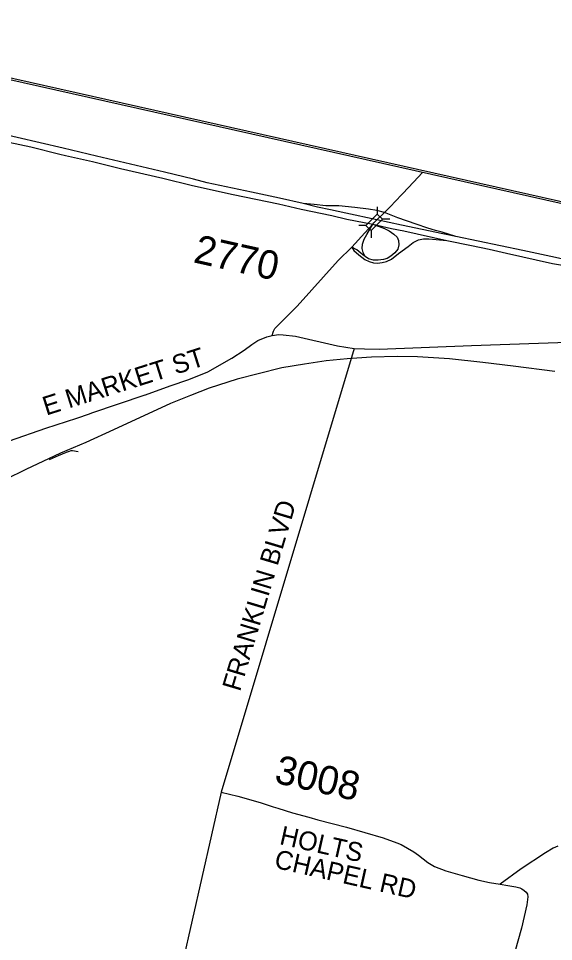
# Model space of a CAD drawing. Extents: x 1784499 to 1786147, y 841097 to 842538.
# Drawn here: x 1784675.3 to 1784800.3, y 842322.5 to 842538 of the extents above; entities that cross this region are included whole.
import ezdxf

# ---------------------------------------------------------------- set-up
doc = ezdxf.new("R2010")
doc.units = 0
for name, color, linetype in [('Exist Railroad Mainline', 7, 'Continuous'), ('Exist Railroad Siding', 7, 'Continuous'), ('Exist Road Primary US Divided Attributed', 7, 'Continuous'), ('Exist Road Primary US Ramp 1 Lane  Attributed', 7, 'Continuous'), ('Exist Road Secondary Structure Standard Bridge CELL', 7, 'Continuous'), ('Exist Road Secondary Type 51 Attributed', 7, 'Continuous'), ('Exist Road Secondary Type 51 Number Label', 7, 'Continuous'), ('Old_Level_40', 7, 'Continuous'), ('Prop DSN Text', 7, 'Continuous'), ('Scratch_Level_3', 7, 'Continuous')]:
    doc.layers.add(name, color=color, linetype=linetype)

msp = doc.modelspace()

# ---------------------------------------------------------------- linework, layer by layer
at = {"layer": 'Exist Railroad Mainline'}
for points in [[(1784800.61, 842455.59), (1784790.82, 842456.82), (1784783.78, 842457.67), (1784775.99, 842458.55), (1784768.54, 842458.99), (1784763.79, 842459.07), (1784757.8, 842458.88), (1784752.06, 842458.55), (1784747.21, 842458.04), (1784742.14, 842457.28), (1784736.83, 842456.42), (1784731.28, 842455.04), (1784726.42, 842453.74), (1784719.87, 842451.65), (1784715.47, 842449.98), (1784710.83, 842448.11), (1784697.49, 842441.98), (1784691.01, 842439.02)], [(1784691.01, 842439.02), (1784685.09, 842436.5), (1784677.01, 842432.69), (1784672.29, 842430.37), (1784671.48, 842430.01)]]:
    msp.add_lwpolyline(points, dxfattribs=at)
at = {"layer": 'Exist Railroad Siding'}
msp.add_lwpolyline([(1784682.54, 842435.04), (1784684.69, 842435.92), (1784686.54, 842436.73), (1784687.22, 842437), (1784687.61, 842437.09), (1784687.96, 842437.11), (1784689.25, 842436.91)], dxfattribs=at)
at = {"layer": 'Exist Road Primary US Divided Attributed'}
for points in [[(1784741.79, 842494.79), (1784736.26, 842496.01), (1784729.74, 842497.43), (1784719.38, 842499.63), (1784716.19, 842500.48), (1784709.41, 842502.1), (1784693.56, 842505.85), (1784685.73, 842507.7), (1784669.58, 842511.47)], [(1784673.09, 842509.12), (1784678.18, 842508.03), (1784685, 842506.29), (1784686.29, 842506), (1784692.62, 842504.55), (1784699.15, 842502.99), (1784709, 842500.66), (1784715.92, 842498.97), (1784725.49, 842496.85), (1784736.04, 842494.67), (1784741.32, 842493.48), (1784748.48, 842491.99), (1784751.97, 842491.13), (1784758.04, 842489.93)], [(1784759.04, 842490.98), (1784751.77, 842492.56), (1784748.17, 842493.27), (1784745.13, 842493.95), (1784741.79, 842494.79)], [(1784758.04, 842489.93), (1784762.45, 842488.96), (1784765.33, 842488.42), (1784775.35, 842486.17)], [(1784777.48, 842487.11), (1784774.4, 842487.73), (1784764.77, 842489.71), (1784759.04, 842490.98)], [(1784775.35, 842486.17), (1784781.15, 842484.98), (1784785.25, 842484.09), (1784789.26, 842483.21), (1784800, 842480.8), (1784801.93, 842480.44), (1784806.17, 842479.41), (1784809.78, 842478.53), (1784812.79, 842477.67), (1784816.72, 842476.6), (1784821.64, 842475.07), (1784831.65, 842472.14), (1784837.18, 842470.45), (1784841.98, 842468.99), (1784850.67, 842466.59), (1784854.86, 842465.36), (1784857.58, 842464.42), (1784859.57, 842463.74), (1784859.86, 842463.6)], [(1784860.26, 842465.03), (1784857.18, 842466.02), (1784855.65, 842466.51), (1784848.95, 842468.65), (1784842.56, 842470.49), (1784829.12, 842474.41), (1784822.96, 842476.2), (1784817.28, 842477.8), (1784812.97, 842479.11), (1784806.72, 842480.83), (1784799.68, 842482.42), (1784793.11, 842483.82), (1784777.48, 842487.11)]]:
    msp.add_lwpolyline(points, dxfattribs=at)
at = {"layer": 'Exist Road Primary US Ramp 1 Lane  Attributed'}
for points in [[(1784760.79, 842492.66), (1784759, 842493.18), (1784757.04, 842493.44), (1784753.88, 842493.84), (1784750.1, 842494.2), (1784747.11, 842494.25), (1784744.35, 842494.51), (1784741.79, 842494.79)], [(1784777.48, 842487.11), (1784774.29, 842488.1), (1784772.71, 842488.45), (1784770.88, 842489.05), (1784768.21, 842489.95), (1784763.95, 842491.46), (1784760.79, 842492.66)], [(1784756.28, 842482.42), (1784755.82, 842483.32), (1784755.58, 842484.3), (1784755.67, 842485.27), (1784756.06, 842486.44), (1784756.71, 842487.56), (1784758.04, 842489.93)], [(1784758.04, 842489.93), (1784760.77, 842488.94), (1784761.85, 842488.37), (1784762.97, 842487.63), (1784763.73, 842486.91), (1784764.05, 842486.16), (1784764.13, 842485.16), (1784763.9, 842484.11), (1784763.21, 842483.23), (1784762.3, 842482.45), (1784761.44, 842481.91), (1784760.53, 842481.68), (1784759.33, 842481.52), (1784758.23, 842481.52), (1784757.07, 842481.84), (1784756.28, 842482.42)], [(1784753.15, 842484.56), (1784753.65, 842483.78), (1784754.77, 842482.79), (1784756.18, 842481.68), (1784757.18, 842481.21), (1784758.21, 842480.91), (1784759.19, 842480.88), (1784760.26, 842481.01), (1784761.3, 842481.26), (1784762.46, 842481.8), (1784764.09, 842483.09), (1784766.3, 842484.74), (1784767.5, 842485.7), (1784768.73, 842486.28), (1784769.89, 842486.51), (1784771.18, 842486.53), (1784775.35, 842486.17)], [(1784756.28, 842482.42), (1784755.7, 842482.82), (1784754.37, 842483.98), (1784753.15, 842484.56)]]:
    msp.add_lwpolyline(points, dxfattribs=at)
at = {"layer": 'Exist Road Secondary Structure Standard Bridge CELL'}
for p, q in [((1784759.09, 842494.02), (1784759.1, 842492.32)), ((1784762.04, 842491.11), (1784760.33, 842491.1)), ((1784756.5, 842489.65), (1784754.79, 842489.64)), ((1784757.71, 842488.45), (1784757.72, 842486.75))]:
    msp.add_line(p, q, dxfattribs=at)
msp.add_lwpolyline([(1784760.33, 842491.1), (1784757.71, 842488.45), (1784756.47, 842489.67), (1784759.1, 842492.32)], close=True, dxfattribs=at)
at = {"layer": 'Exist Road Secondary Type 51 Attributed'}
for p, q in [((1784759.04, 842490.98), (1784760.79, 842492.66)), ((1784753.74, 842460.96), (1784722.62, 842357.35)), ((1784722.62, 842357.35), (1784707.72, 842291.21))]:
    msp.add_line(p, q, dxfattribs=at)
for points in [[(1784760.79, 842492.66), (1784762.41, 842494.31), (1784763.15, 842495.08), (1784765.11, 842497.09), (1784767.56, 842499.79), (1784769.67, 842502.01)], [(1784753.15, 842484.56), (1784756.21, 842487.95), (1784758.04, 842489.93)], [(1784758.04, 842489.93), (1784758.34, 842490.24), (1784759.04, 842490.98)], [(1784734.54, 842463.99), (1784734.87, 842464.94), (1784735.2, 842465.61), (1784736.77, 842467.15), (1784740.4, 842470.85), (1784749.94, 842481.44), (1784753.15, 842484.56)], [(1784734.54, 842463.99), (1784736.08, 842464.19), (1784737.14, 842464.13), (1784740, 842463.79), (1784749.8, 842461.54), (1784753.74, 842460.96), (1784756.09, 842460.82), (1784759.54, 842460.81), (1784781.14, 842461.65), (1784805.69, 842462.5)], [(1784664.63, 842436.41), (1784681.73, 842442.31), (1784688.97, 842444.7), (1784691.86, 842445.71), (1784692.47, 842445.92), (1784704.92, 842450.09), (1784704.97, 842450.11), (1784710.73, 842452.18), (1784715.06, 842453.69), (1784719.54, 842455.52), (1784725.16, 842458.71), (1784728.01, 842460.52), (1784729.8, 842461.9), (1784731.2, 842462.82), (1784733.29, 842463.66), (1784734.54, 842463.99)], [(1784722.62, 842357.35), (1784726.58, 842356.46), (1784731.72, 842354.95), (1784734.82, 842353.95), (1784735.9, 842353.59), (1784739.32, 842352.57), (1784743.15, 842351.55), (1784745.21, 842350.91), (1784751.9, 842349.16), (1784760.49, 842346.69), (1784763.71, 842345.54), (1784764.7, 842345.14), (1784767.64, 842343.42), (1784768.71, 842342.64), (1784770.92, 842340.96), (1784772.45, 842340.02), (1784775.15, 842338.96), (1784778.95, 842337.9), (1784782.81, 842336.85), (1784785.29, 842336.28), (1784787.81, 842335.88)], [(1784801.25, 842344.77), (1784800.23, 842344.28), (1784798.43, 842343.23), (1784792.71, 842339.5), (1784787.81, 842335.88)], [(1784787.81, 842335.88), (1784789.61, 842335.61), (1784791.47, 842335.23), (1784792.38, 842334.99), (1784792.91, 842334.77), (1784793.45, 842334.43), (1784793.9, 842334), (1784794.16, 842333.56), (1784794.27, 842332.96), (1784794.01, 842331.03), (1784792.79, 842325.62), (1784791.25, 842320.11), (1784789.8, 842313.98), (1784787.86, 842306.62), (1784785.91, 842299.11), (1784784.3, 842292.16), (1784783.32, 842285.88), (1784782.51, 842281.97), (1784781.55, 842279.27), (1784779.73, 842275.55), (1784777.3, 842271.04), (1784776.75, 842269.5), (1784776.34, 842266.99), (1784775.93, 842264.5)]]:
    msp.add_lwpolyline(points, dxfattribs=at)
at = {"layer": 'Old_Level_40'}
msp.add_line((1784611.59, 842537.98), (1785099.64, 842428.53), dxfattribs=at)
at = {"layer": 'Scratch_Level_3'}
msp.add_lwpolyline([(1785039.41, 842390.83), (1785050.23, 842439.1), (1784611.48, 842537.49), (1784510.23, 842085.98), (1784998.27, 841976.54), (1785088.7, 842379.78)], close=True, dxfattribs=at)

# ---------------------------------------------------------------- texts
at = {"layer": 'Exist Road Secondary Type 51 Number Label'}
for s, p in [('2770', (1784715.93, 842481.09)), ('3008', (1784734.84, 842359.61))]:
    msp.add_text(s, height=6.665, rotation=347.3599, dxfattribs=at).set_placement(p)
at = {"layer": 'Prop DSN Text'}
for s, height, rotation, p in [('E MARKET ST', 4.3971, 17.5536, (1784681.78, 842445.25)), ('RANKLIN BLVD', 4.3971, 73.3546, (1784728.03, 842384.01)), ('F', 4.4, 73.3546, (1784727.03, 842380.68)), ('HOLTS', 4.397, 347.336, (1784736.08, 842345.26)), ('CHAPEL RD', 4.397, 347.336, (1784734.84, 842339.75))]:
    msp.add_text(s, height=height, rotation=rotation, dxfattribs=at).set_placement(p)

doc.saveas('drawing.dxf')
